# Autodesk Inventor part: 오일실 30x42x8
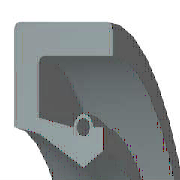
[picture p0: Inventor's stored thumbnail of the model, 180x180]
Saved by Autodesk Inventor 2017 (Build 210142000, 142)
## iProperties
IsCustomPart: 0
Created: 2009-02
Part Number: 오일실 30x42x8
Material: 고무
Document SubType Name: Modeling
Standard: KS B 2804
Designer: mdu
Standards Organization: KS
Language: ko-KR
Size Designation: S - 30 42 8
Categories: <MemberInstance><Categories><Category DisplayName="샤프트 부품" InternalName="7f7aeb1f-a693-4053-b835-cee3144e0d98" Mnemonic="SHFT"><Category DisplayName="실링" Intern
Density: 0.93 g/cm^3
Appearance: 고무 - 검은색 - 버전 1.1
Author: mdu
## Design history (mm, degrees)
revolve "본체" stored, may be unused: angle "d17" = 90 deg
revolve "스프링1" stored, may be unused: angle "d18" = 90 deg
body "Solid1"
sketch "스케치1"
  geometry: L1 (0, 21)-(8, 21); L2 (8, 21)-(8, 19.75); L3 (8, 19.75)-(1.75, 19.75); L4 (0, 21)-(0, 17.1); L5 (0, 17.1)-(1.75, 16.75); L6 (1.75, 16.75)-(4.9, 15); L7 (4.9, 15)-(0, 15); L8 (6.3, 15.875)-(6.3, 17.1); L9 (0, 0)-(9.586, 0) reference; L10 (4.9, 15)-(6.3, 15.875); L11 (0, 18)-(0, -3) reference; L12 (-1.917, 0)-(11.503, 0) reference; L13 (4.2, 17.1)-(1.75, 17.59); L14 (1.75, 17.59)-(1.75, 19.75); L15 (6.3, 17.1)-(5.6, 17.1); C1 r 0.455 at (4.9, 17.1); A1 r 0.7 centre (4.9, 17.1) between (5.6, 17.1) and (4.2, 17.1)
  constraints: 26 end point, 5 horizontal alignment, 4 perpendicular, 2 centre point, 2 collinear, 2 horizontal, 2 parallel, 2 point on circle, 2 point on line, 2 vertical alignment, 1 coincident
  dimensions: "d0" = 42 diameter of L1 L9 (= SD2); "d1" = 31.75 diameter of L8.start L9 (= ABDM); "d2" = 1.25 distance of L1.end L2.end (computed from SD); "d3" = 0.91 diameter of C1 (= SPDI); "d4" = 1.4 diameter of A1 (= SPDA); "d5" = 30 diameter of L6.end L9 (= NND); "d6" = 33.5 diameter of L5.end L9 (= TKDM); "d7" = 34.2 diameter of L4.end L9 (= HLDM); "d8" = 4.9 distance from line of C1.centre L4 (= SPDST); "d9" = 6.3 distance between parallel lines of L8 L4 (= SDI); "d10" = 8 distance between parallel lines of L2 L4 (= SWDT); "d12" = 1.75 distance between parallel lines of L14 L4 (= SD)
fillet "모깎기1" dims "d11" = 0.4 (= RR)
other parameters: "SD2" = 42 [user parameter; used in 1 equation term], "SWDT" = 8 [user parameter; used in 1 equation term], "RR" = 0.4 [user parameter; used in 1 equation term], "SD" = 1.75 [user parameter; used in 2 equation terms], "NND" = 30 [user parameter; used in 1 equation term], "SPDA" = 1.4 [user parameter; used in 1 equation term], "SPDI" = 0.91 [user parameter; used in 1 equation term], "TKDM" = 33.5 [user parameter; used in 1 equation term], "HLDM" = 34.2 [user parameter; used in 1 equation term], "ABDM" = 31.75 [user parameter; used in 1 equation term], "SDI" = 6.3 [user parameter; used in 1 equation term], "SPDST" = 4.9 [user parameter; used in 1 equation term], "d13" = 0, "d14" = 0, "d15" = 0, "LAB" = 0.35 [user parameter]
